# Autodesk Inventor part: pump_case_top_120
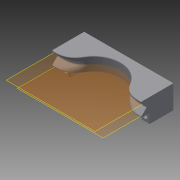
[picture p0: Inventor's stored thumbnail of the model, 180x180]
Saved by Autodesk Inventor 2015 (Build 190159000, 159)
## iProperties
Created: 2017-07
Part Number: pump_case_top_120
Material: Generic
Document SubType Name: Modeling
Designer: jonas
Density: 1 g/cm^3
Appearance: Default
Author: jonas
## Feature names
1. Extrusion1
2. Sweep1
3. Mirror1
4. Fillet7
5. Fillet10
6. Fillet11
7. Extrusion2
8. Chamfer1
9. Hole1
## Parameters: d0 = 120 deg, d2 = 0, d3 = 90 deg, d5 = 0, d6 = 0, d9 = 32 mm, d13 = 3 mm, d15 = 1 mm, d18 = 4 mm, d19 = 0.5 mm, d22 = 6 mm, d26 = 0, d27 = 1 mm, d28 = 2 mm, d29 = 45 deg, d30 = 7 mm, d32 = 0.2 mm, d33 = 7 mm, d36 = 0.2 mm, d37 = 3.5 mm, d38 = 6 mm, d39 = 4 mm, d40 = 2 mm, d41 = 90 deg, d42 = 8 mm, d43 = 118 deg
